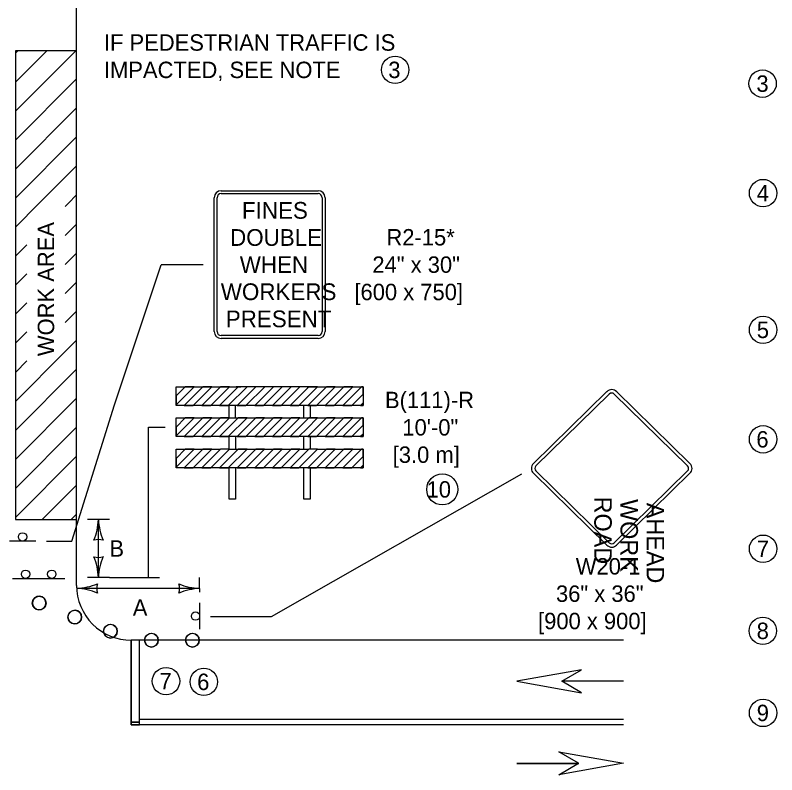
# Model space of a CAD drawing. Extents: x 49991.4 to 50021, y 49987.6 to 50011.4.
# Drawn here: x 50003.139 to 50005.923, y 50005.551 to 50008.327 of the extents above; entities that cross this region are included whole.
import ezdxf

# ---------------------------------------------------------------- set-up
doc = ezdxf.new("R2010")
doc.units = 0
for name, color, linetype in [('Level 1', 7, 'Continuous'), ('Level 2', 7, 'Continuous'), ('Level 3', 7, 'Continuous')]:
    doc.layers.add(name, color=color, linetype=linetype)

# ---------------------------------------------------------------- blocks, each defined once
blk = doc.blocks.new('ARR')
at = {"layer": 'Level 3'}
for centre, radius, start, end in [((1.53, 37.02), 37.05, 247.456, 267.6395), ((-21.37, 0), 9.13, 342.1388, 17.8612), ((1.92, -38.79), 38.83, 92.8273, 112.0772)]:
    blk.add_arc(centre, radius, start, end, dxfattribs=at)

msp = doc.modelspace()

# ---------------------------------------------------------------- linework, layer by layer
at = {"layer": 'Level 1'}
for p, q in [((50003.3635, 50006.2425), (50003.3635, 50008.3654)), ((50003.1396, 50008.1883), (50003.1483, 50008.197)), ((50003.1396, 50008.0822), (50003.2544, 50008.197)), ((50003.1396, 50007.9761), (50003.3604, 50008.197)), ((50003.1396, 50007.8701), (50003.3635, 50008.094)), ((50003.1396, 50007.764), (50003.3635, 50007.9879)), ((50003.1396, 50007.6579), (50003.3635, 50007.8818)), ((50003.2258, 50007.6381), (50003.3635, 50007.7758)), ((50003.8922, 50007.6852), (50004.2466, 50007.6852)), ((50003.8922, 50007.6747), (50004.2466, 50007.6747)), ((50004.0694, 50007.6852), (50004.0694, 50007.6852)), ((50003.3325, 50007.6387), (50003.3635, 50007.6697)), ((50003.8668, 50007.1705), (50003.8668, 50007.6599)), ((50003.8774, 50007.1705), (50003.8774, 50007.6599)), ((50004.2614, 50007.6599), (50004.2614, 50007.1705)), ((50004.2719, 50007.6599), (50004.2719, 50007.1705)), ((50003.1396, 50007.5519), (50003.2258, 50007.6381)), ((50003.3215, 50007.6278), (50003.3325, 50007.6387)), ((50003.3215, 50007.5217), (50003.3635, 50007.5636)), ((50003.1396, 50007.4458), (50003.1815, 50007.4878)), ((50003.3215, 50007.4156), (50003.3635, 50007.4576)), ((50003.1396, 50007.3397), (50003.1815, 50007.3817)), ((50003.3215, 50007.3096), (50003.3635, 50007.3515)), ((50003.1396, 50007.2337), (50003.1815, 50007.2756)), ((50003.3215, 50007.2035), (50003.3635, 50007.2454)), ((50003.1396, 50007.1276), (50003.1815, 50007.1696)), ((50004.2466, 50007.1557), (50003.8922, 50007.1557)), ((50004.2466, 50007.1452), (50003.8922, 50007.1452)), ((50003.3215, 50007.0974), (50003.3635, 50007.1394)), ((50003.1396, 50006.9155), (50003.3215, 50007.0974)), ((50003.1396, 50007.0215), (50003.1815, 50007.0635)), ((50003.1396, 50006.8094), (50003.3635, 50007.0333)), ((50003.7274, 50006.9029), (50003.7932, 50006.9687)), ((50003.7274, 50006.9351), (50003.761, 50006.9687)), ((50003.761, 50006.9687), (50003.7274, 50006.9351)), ((50003.7274, 50006.9029), (50003.7932, 50006.9687)), ((50003.7571, 50006.9003), (50003.8255, 50006.9687)), ((50003.8255, 50006.9687), (50003.7571, 50006.9003)), ((50003.7893, 50006.9003), (50003.8577, 50006.9687)), ((50003.7893, 50006.9003), (50003.8577, 50006.9687)), ((50003.8216, 50006.9003), (50003.89, 50006.9687)), ((50003.89, 50006.9687), (50003.8216, 50006.9003)), ((50003.8538, 50006.9003), (50003.9222, 50006.9687)), ((50003.8538, 50006.9003), (50003.9222, 50006.9687)), ((50003.886, 50006.9003), (50003.9544, 50006.9687)), ((50003.9183, 50006.9003), (50003.9867, 50006.9687)), ((50003.9326, 50006.9687), (50003.9639, 50006.9687)), ((50004.1919, 50006.9687), (50003.9468, 50006.9687)), ((50003.9507, 50006.9003), (50004.0191, 50006.9687)), ((50003.9829, 50006.9003), (50004.0513, 50006.9687)), ((50004.0151, 50006.9003), (50004.0835, 50006.9687)), ((50004.0473, 50006.9003), (50004.1157, 50006.9687)), ((50004.0795, 50006.9003), (50004.1479, 50006.9687)), ((50004.1117, 50006.9003), (50004.1801, 50006.9687)), ((50004.1439, 50006.9003), (50004.2123, 50006.9687)), ((50004.2123, 50006.9687), (50004.1724, 50006.9687)), ((50004.1761, 50006.9003), (50004.2445, 50006.9687)), ((50004.2084, 50006.9003), (50004.2768, 50006.9687)), ((50004.2768, 50006.9687), (50004.2084, 50006.9003)), ((50004.2406, 50006.9003), (50004.309, 50006.9687)), ((50004.2406, 50006.9003), (50004.309, 50006.9687)), ((50004.2728, 50006.9003), (50004.3412, 50006.9687)), ((50004.3412, 50006.9687), (50004.2728, 50006.9003)), ((50004.3051, 50006.9003), (50004.3735, 50006.9687)), ((50004.3051, 50006.9003), (50004.3735, 50006.9687)), ((50004.3374, 50006.9003), (50004.4058, 50006.9687)), ((50004.4058, 50006.9687), (50004.3374, 50006.9003)), ((50005.0342, 50006.6884), (50005.3022, 50006.9509)), ((50005.338, 50006.9509), (50005.606, 50006.6884)), ((50003.1396, 50006.7034), (50003.3635, 50006.9272)), ((50004.3696, 50006.9003), (50004.4113, 50006.9421)), ((50004.3696, 50006.9003), (50004.4113, 50006.9421)), ((50005.0428, 50006.6796), (50005.3108, 50006.9422)), ((50005.3295, 50006.9422), (50005.5974, 50006.6796)), ((50003.944, 50006.8548), (50003.944, 50006.9003)), ((50004.1948, 50006.8548), (50004.1948, 50006.9003)), ((50004.4018, 50006.9003), (50004.4113, 50006.9098)), ((50004.4113, 50006.9098), (50004.4018, 50006.9003)), ((50003.7274, 50006.7889), (50003.7932, 50006.8548)), ((50003.7274, 50006.8211), (50003.761, 50006.8548)), ((50003.761, 50006.8548), (50003.7274, 50006.8211)), ((50003.7274, 50006.7889), (50003.7932, 50006.8548)), ((50003.7571, 50006.7864), (50003.8255, 50006.8548)), ((50003.8255, 50006.8548), (50003.7571, 50006.7864)), ((50003.7893, 50006.7864), (50003.8577, 50006.8548)), ((50003.7893, 50006.7864), (50003.8577, 50006.8548)), ((50003.8216, 50006.7864), (50003.89, 50006.8548)), ((50003.89, 50006.8548), (50003.8216, 50006.7864)), ((50003.8538, 50006.7864), (50003.9222, 50006.8548)), ((50003.8538, 50006.7864), (50003.9222, 50006.8548)), ((50003.886, 50006.7864), (50003.9544, 50006.8548)), ((50003.9183, 50006.7864), (50003.9867, 50006.8548)), ((50003.9505, 50006.7864), (50004.0189, 50006.8548)), ((50003.9827, 50006.7864), (50004.0511, 50006.8548)), ((50004.0149, 50006.7864), (50004.0833, 50006.8548)), ((50004.0472, 50006.7864), (50004.1156, 50006.8548)), ((50004.0795, 50006.7864), (50004.1479, 50006.8548)), ((50004.1117, 50006.7864), (50004.1801, 50006.8548)), ((50004.1439, 50006.7864), (50004.2062, 50006.8486)), ((50004.2062, 50006.8164), (50004.2445, 50006.8548)), ((50004.2062, 50006.8486), (50004.2123, 50006.8548)), ((50004.2084, 50006.7864), (50004.2768, 50006.8548)), ((50004.2768, 50006.8548), (50004.2084, 50006.7864)), ((50004.2406, 50006.7864), (50004.309, 50006.8548)), ((50004.2406, 50006.7864), (50004.309, 50006.8548)), ((50004.2728, 50006.7864), (50004.3412, 50006.8548)), ((50004.3412, 50006.8548), (50004.2728, 50006.7864)), ((50004.3051, 50006.7864), (50004.3735, 50006.8548)), ((50004.3051, 50006.7864), (50004.3735, 50006.8548)), ((50004.3374, 50006.7864), (50004.4058, 50006.8548)), ((50004.4058, 50006.8548), (50004.3374, 50006.7864)), ((50003.1396, 50006.5973), (50003.3635, 50006.8212)), ((50004.1761, 50006.7864), (50004.2062, 50006.8164)), ((50004.3696, 50006.7864), (50004.4113, 50006.8281)), ((50004.3696, 50006.7864), (50004.4113, 50006.8281)), ((50004.4018, 50006.7864), (50004.4113, 50006.7959)), ((50004.4113, 50006.7959), (50004.4018, 50006.7864)), ((50003.7274, 50006.6749), (50003.7932, 50006.7408)), ((50003.7274, 50006.7072), (50003.761, 50006.7408)), ((50003.761, 50006.7408), (50003.7274, 50006.7072)), ((50003.7274, 50006.6749), (50003.7932, 50006.7408)), ((50003.7571, 50006.6724), (50003.8255, 50006.7408)), ((50003.8255, 50006.7408), (50003.7571, 50006.6724)), ((50003.7893, 50006.6724), (50003.8577, 50006.7408)), ((50003.7893, 50006.6724), (50003.8577, 50006.7408)), ((50003.8216, 50006.6724), (50003.89, 50006.7408)), ((50003.89, 50006.7408), (50003.8216, 50006.6724)), ((50003.8538, 50006.6724), (50003.9222, 50006.7408)), ((50003.8538, 50006.6724), (50003.9222, 50006.7408)), ((50003.886, 50006.6724), (50003.9544, 50006.7408)), ((50003.9544, 50006.7408), (50003.886, 50006.6724)), ((50003.9183, 50006.6724), (50003.9867, 50006.7408)), ((50003.9183, 50006.6724), (50003.9867, 50006.7408)), ((50003.9505, 50006.6724), (50004.0189, 50006.7408)), ((50004.0189, 50006.7408), (50003.9505, 50006.6724)), ((50003.9827, 50006.6724), (50004.0511, 50006.7408)), ((50003.9827, 50006.6724), (50004.0511, 50006.7408)), ((50004.0149, 50006.6724), (50004.0833, 50006.7408)), ((50004.0833, 50006.7408), (50004.0149, 50006.6724)), ((50004.0472, 50006.6724), (50004.1156, 50006.7408)), ((50004.0472, 50006.6724), (50004.1156, 50006.7408)), ((50004.0795, 50006.6724), (50004.1479, 50006.7408)), ((50004.1479, 50006.7408), (50004.0795, 50006.6724)), ((50004.1117, 50006.6724), (50004.1801, 50006.7408)), ((50004.1117, 50006.6724), (50004.1801, 50006.7408)), ((50004.1439, 50006.6724), (50004.2123, 50006.7408)), ((50004.2123, 50006.7408), (50004.1439, 50006.6724)), ((50004.1761, 50006.6724), (50004.2445, 50006.7408)), ((50004.1761, 50006.6724), (50004.2445, 50006.7408)), ((50004.2084, 50006.6724), (50004.2768, 50006.7408)), ((50004.2768, 50006.7408), (50004.2084, 50006.6724)), ((50004.2406, 50006.6724), (50004.309, 50006.7408)), ((50004.2406, 50006.6724), (50004.309, 50006.7408)), ((50004.2728, 50006.6724), (50004.3412, 50006.7408)), ((50004.3412, 50006.7408), (50004.2728, 50006.6724)), ((50004.3051, 50006.6724), (50004.3735, 50006.7408)), ((50004.3051, 50006.6724), (50004.3735, 50006.7408)), ((50004.3374, 50006.6724), (50004.4058, 50006.7408)), ((50004.4058, 50006.7408), (50004.3374, 50006.6724)), ((50003.1396, 50006.4912), (50003.3635, 50006.7151)), ((50004.3696, 50006.6724), (50004.4113, 50006.7141)), ((50004.3696, 50006.6724), (50004.4113, 50006.7141)), ((50004.4018, 50006.6724), (50004.4113, 50006.6819)), ((50004.4113, 50006.6819), (50004.4018, 50006.6724)), ((50005.3022, 50006.3899), (50005.0342, 50006.6525)), ((50005.3108, 50006.3987), (50005.0428, 50006.6612)), ((50005.5974, 50006.6612), (50005.3295, 50006.3987)), ((50005.606, 50006.6525), (50005.338, 50006.3899)), ((50003.238, 50006.4836), (50003.3635, 50006.609)), ((50003.3441, 50006.4836), (50003.3635, 50006.503)), ((50003.2141, 50006.405), (50003.1181, 50006.405)), ((50003.1288, 50006.2684), (50003.2248, 50006.2684)), ((50003.2248, 50006.2684), (50003.3208, 50006.2684)), ((50003.8135, 50006.1786), (50003.8135, 50006.0826)), ((50005.3635, 50006.0426), (50003.5635, 50006.0426)), ((50003.5635, 50005.7326), (50003.5635, 50006.0426)), ((50003.5935, 50005.7326), (50003.5935, 50006.0426)), ((50005.3635, 50005.8927), (50005.1376, 50005.8927)), ((50005.3635, 50005.8923), (50005.1376, 50005.8923)), ((50005.3635, 50005.7526), (50003.5935, 50005.7526)), ((50003.5935, 50005.7427), (50003.5635, 50005.7427)), ((50005.3635, 50005.7326), (50003.5635, 50005.7326)), ((50004.9734, 50005.5927), (50005.1993, 50005.5927)), ((50004.9734, 50005.5923), (50005.1993, 50005.5923))]:
    msp.add_line(p, q, dxfattribs=at)
for points in [[(50003.3635, 50008.197), (50003.1396, 50008.197), (50003.1396, 50006.4836), (50003.3635, 50006.4836)], [(50004.2062, 50006.9003), (50003.7274, 50006.9003), (50003.7274, 50006.9687), (50003.9326, 50006.9687)], [(50003.7932, 50006.9687), (50003.761, 50006.9687)], [(50003.8577, 50006.9687), (50003.8255, 50006.9687)], [(50003.9867, 50006.9687), (50003.9639, 50006.9687), (50003.9544, 50006.9687), (50003.886, 50006.9003), (50003.9183, 50006.9003), (50003.9867, 50006.9687)], [(50003.9222, 50006.9687), (50003.89, 50006.9687)], [(50004.0513, 50006.9687), (50004.0191, 50006.9687), (50003.9507, 50006.9003), (50003.9829, 50006.9003), (50004.0513, 50006.9687)], [(50004.1157, 50006.9687), (50004.0835, 50006.9687), (50004.0151, 50006.9003), (50004.0473, 50006.9003), (50004.1157, 50006.9687)], [(50004.1801, 50006.9687), (50004.1724, 50006.9687), (50004.1479, 50006.9687), (50004.0795, 50006.9003), (50004.1117, 50006.9003), (50004.1801, 50006.9687)], [(50004.1439, 50006.9003), (50004.1761, 50006.9003), (50004.2445, 50006.9687), (50004.2123, 50006.9687), (50004.1439, 50006.9003)], [(50004.2062, 50006.9687), (50004.4113, 50006.9687), (50004.4113, 50006.9003), (50004.2062, 50006.9003)], [(50004.309, 50006.9687), (50004.2768, 50006.9687)], [(50004.3735, 50006.9687), (50004.3412, 50006.9687)], [(50004.4113, 50006.9421), (50004.4113, 50006.9687), (50004.4058, 50006.9687)], [(50003.7274, 50006.9351), (50003.7274, 50006.9029)], [(50003.7571, 50006.9003), (50003.7893, 50006.9003)], [(50003.8216, 50006.9003), (50003.8538, 50006.9003)], [(50003.9212, 50006.8547), (50003.9212, 50006.9003)], [(50004.2084, 50006.9003), (50004.2406, 50006.9003)], [(50004.2176, 50006.9003), (50004.2176, 50006.8548)], [(50004.2728, 50006.9003), (50004.3051, 50006.9003)], [(50004.3374, 50006.9003), (50004.3696, 50006.9003)], [(50004.4018, 50006.9003), (50004.4113, 50006.9003), (50004.4113, 50006.9098)], [(50004.2062, 50006.8548), (50004.4113, 50006.8548), (50004.4113, 50006.7864), (50003.7274, 50006.7864), (50003.7274, 50006.8548), (50004.2062, 50006.8548)], [(50003.7932, 50006.8548), (50003.761, 50006.8548)], [(50003.8577, 50006.8548), (50003.8255, 50006.8548)], [(50003.9867, 50006.8548), (50003.9544, 50006.8548), (50003.886, 50006.7864), (50003.9183, 50006.7864), (50003.9867, 50006.8548)], [(50003.9222, 50006.8548), (50003.89, 50006.8548)], [(50004.0511, 50006.8548), (50004.0189, 50006.8548), (50003.9505, 50006.7864), (50003.9827, 50006.7864), (50004.0511, 50006.8548)], [(50004.1156, 50006.8548), (50004.0833, 50006.8548), (50004.0149, 50006.7864), (50004.0472, 50006.7864), (50004.1156, 50006.8548)], [(50004.1801, 50006.8548), (50004.1479, 50006.8548), (50004.0795, 50006.7864), (50004.1117, 50006.7864), (50004.1801, 50006.8548)], [(50004.1439, 50006.7864), (50004.1761, 50006.7864), (50004.2062, 50006.8164), (50004.2445, 50006.8548), (50004.2176, 50006.8548), (50004.2123, 50006.8548), (50004.2062, 50006.8486), (50004.1439, 50006.7864)], [(50004.309, 50006.8548), (50004.2768, 50006.8548)], [(50004.3735, 50006.8548), (50004.3412, 50006.8548)], [(50004.4113, 50006.8281), (50004.4113, 50006.8548), (50004.4058, 50006.8548)], [(50003.7274, 50006.8211), (50003.7274, 50006.7889)], [(50003.7571, 50006.7864), (50003.7893, 50006.7864)], [(50003.8216, 50006.7864), (50003.8538, 50006.7864)], [(50003.9212, 50006.7408), (50003.9212, 50006.7864)], [(50003.944, 50006.7864), (50003.944, 50006.7408)], [(50004.1948, 50006.7408), (50004.1948, 50006.7864)], [(50004.2084, 50006.7864), (50004.2406, 50006.7864)], [(50004.2176, 50006.7864), (50004.2176, 50006.7408)], [(50004.2728, 50006.7864), (50004.3051, 50006.7864)], [(50004.3374, 50006.7864), (50004.3696, 50006.7864)], [(50004.4018, 50006.7864), (50004.4113, 50006.7864), (50004.4113, 50006.7959)], [(50004.2445, 50006.7408), (50004.4113, 50006.7408), (50004.4113, 50006.6724), (50003.7274, 50006.6724), (50003.7274, 50006.7408), (50003.89, 50006.7408)], [(50003.7932, 50006.7408), (50003.761, 50006.7408)], [(50003.8577, 50006.7408), (50003.8255, 50006.7408)], [(50003.9222, 50006.7408), (50003.89, 50006.7408)], [(50003.9222, 50006.7408), (50004.2123, 50006.7408)], [(50003.9867, 50006.7408), (50003.9544, 50006.7408)], [(50004.0511, 50006.7408), (50004.0189, 50006.7408)], [(50004.1156, 50006.7408), (50004.0833, 50006.7408)], [(50004.1801, 50006.7408), (50004.1479, 50006.7408)], [(50004.2445, 50006.7408), (50004.2123, 50006.7408)], [(50004.309, 50006.7408), (50004.2768, 50006.7408)], [(50004.3735, 50006.7408), (50004.3412, 50006.7408)], [(50004.4113, 50006.7141), (50004.4113, 50006.7408), (50004.4058, 50006.7408)], [(50003.7274, 50006.7072), (50003.7274, 50006.6749)], [(50003.7571, 50006.6724), (50003.7893, 50006.6724)], [(50003.8216, 50006.6724), (50003.8538, 50006.6724)], [(50003.886, 50006.6724), (50003.9183, 50006.6724)], [(50003.944, 50006.6723), (50003.944, 50006.5583), (50003.9212, 50006.5583), (50003.9212, 50006.6723)], [(50003.9505, 50006.6724), (50003.9827, 50006.6724)], [(50004.0149, 50006.6724), (50004.0472, 50006.6724)], [(50004.0795, 50006.6724), (50004.1117, 50006.6724)], [(50004.1439, 50006.6724), (50004.1761, 50006.6724)], [(50004.2176, 50006.6723), (50004.2176, 50006.5583), (50004.1948, 50006.5583), (50004.1948, 50006.6723)], [(50004.2084, 50006.6724), (50004.2406, 50006.6724)], [(50004.2728, 50006.6724), (50004.3051, 50006.6724)], [(50004.3374, 50006.6724), (50004.3696, 50006.6724)], [(50004.4018, 50006.6724), (50004.4113, 50006.6724), (50004.4113, 50006.6819)], [(50003.5935, 50006.0426), (50003.5635, 50006.0426), (50003.5635, 50005.7427), (50003.5935, 50005.7427), (50003.5935, 50006.0426)], [(50003.5635, 50005.7427), (50003.5635, 50005.7326), (50003.5935, 50005.7326), (50003.5935, 50005.7427), (50003.5635, 50005.7427)]]:
    msp.add_lwpolyline(points, dxfattribs=at)
for points in [[(50005.2099, 50005.9343), (50004.9734, 50005.8927), (50005.2099, 50005.8507), (50005.1377, 50005.8927)], [(50005.127, 50005.6343), (50005.3635, 50005.5927), (50005.127, 50005.5507), (50005.1992, 50005.5927)]]:
    msp.add_lwpolyline(points, close=True, dxfattribs=at)
for centre, radius in [((50003.1661, 50006.4202), 0.0152), ((50003.1768, 50006.2836), 0.0152), ((50003.2728, 50006.2836), 0.0152), ((50003.2267, 50006.1783), 0.025), ((50003.3569, 50006.1269), 0.025), ((50003.7983, 50006.1306), 0.0152), ((50003.4872, 50006.0755), 0.025), ((50003.6372, 50006.0426), 0.025), ((50003.7872, 50006.0426), 0.025)]:
    msp.add_circle(centre, radius, dxfattribs=at)
for centre, radius, start, end in [((50003.8922, 50007.6599), 0.0253, 90, 180), ((50003.8922, 50007.6599), 0.0148, 90, 180), ((50004.2466, 50007.6599), 0.0253, 0, 90), ((50004.2466, 50007.6599), 0.0148, 0, 90), ((50003.8922, 50007.1705), 0.0253, 180, 270), ((50003.8922, 50007.1705), 0.0148, 180, 270), ((50004.2466, 50007.1705), 0.0148, 270, 360), ((50004.2466, 50007.1705), 0.0253, 270, 360), ((50003.5635, 50006.2426), 0.2, 180, 270.0006), ((50003.2267, 50006.1783), 0.025, 357.0759, 177.0759), ((50003.2267, 50006.1783), 0.025, 177.0759, 357.0759), ((50003.3569, 50006.1269), 0.025, 357.0759, 177.0759), ((50003.3569, 50006.1269), 0.025, 177.0759, 357.0759), ((50003.4872, 50006.0755), 0.025, 357.0759, 177.0759), ((50003.4872, 50006.0755), 0.025, 177.0759, 357.0759), ((50003.6372, 50006.0426), 0.025, 357.0759, 177.0759), ((50003.7872, 50006.0426), 0.025, 357.0759, 177.0759), ((50003.6372, 50006.0426), 0.025, 177.0759, 357.0759), ((50003.7872, 50006.0426), 0.025, 177.0759, 357.0759)]:
    msp.add_arc(centre, radius, start, end, dxfattribs=at)
for centre, major_axis, ratio, start_param, end_param in [((50005.3202, 50006.933), (-0.0255, 0), 0.98963, 3.926991, 5.497787), ((50005.3202, 50006.933), (-0.0132, 0), 0.98, 3.926991, 5.497787), ((50005.0522, 50006.6704), (-0.0255, 0), 0.98963, 5.497787, 7.068583), ((50005.0522, 50006.6704), (-0.0132, 0), 0.98, 5.497787, 7.068583), ((50005.5881, 50006.6704), (0.0132, 0), 0.98, 5.497795, 7.068583), ((50005.5881, 50006.6704), (0.0255, 0), 0.98963, 5.497795, 7.068583), ((50005.3202, 50006.4078), (-0.0132, 0), 0.98, 0.785394, 2.356194), ((50005.3202, 50006.4078), (-0.0255, 0), 0.98963, 0.785394, 2.356194)]:
    msp.add_ellipse(centre, major_axis=major_axis, ratio=ratio, start_param=start_param, end_param=end_param, dxfattribs=at)
at = {"layer": 'Level 2'}
for centre, radius in [((50004.5284, 50008.127), 0.0501), ((50005.8718, 50008.0767), 0.0501), ((50005.8734, 50007.6767), 0.0501), ((50005.8734, 50007.1767), 0.0501), ((50005.8734, 50006.7767), 0.0501), ((50004.7007, 50006.5937), 0.0569), ((50005.8734, 50006.3767), 0.0501), ((50005.8728, 50006.0767), 0.0501), ((50003.6905, 50005.8928), 0.0501), ((50003.8289, 50005.8903), 0.0501), ((50005.8734, 50005.7767), 0.0501)]:
    msp.add_circle(centre, radius, dxfattribs=at)
at = {"layer": 'Level 3'}
for p, q in [((50003.502, 50006.9032), (50003.6726, 50007.4142)), ((50003.6726, 50007.4152), (50003.8268, 50007.4152)), ((50003.3463, 50006.405), (50003.502, 50006.9032)), ((50003.6267, 50006.8206), (50003.6874, 50006.8206)), ((50003.6267, 50006.2717), (50003.6267, 50006.8206)), ((50004.0767, 50006.129), (50004.992, 50006.6506)), ((50003.4835, 50006.4836), (50003.4035, 50006.4836)), ((50003.4435, 50006.2717), (50003.4435, 50006.4836)), ((50003.2541, 50006.405), (50003.3463, 50006.405)), ((50003.4835, 50006.2717), (50003.4035, 50006.2717)), ((50003.4835, 50006.2717), (50003.6667, 50006.2717)), ((50003.8135, 50006.2317), (50003.8135, 50006.2717)), ((50003.8135, 50006.2317), (50003.3638, 50006.2317)), ((50003.8135, 50006.2317), (50003.8135, 50006.2186)), ((50003.8535, 50006.129), (50004.0767, 50006.129))]:
    msp.add_line(p, q, dxfattribs=at)
for centre, radius, start, end in [((50003.2213, 50006.4928), 0.2223, 337.456, 357.6395), ((50003.6762, 50006.4951), 0.233, 182.8273, 202.0772), ((50003.4435, 50006.3554), 0.0548, 72.1388, 107.8612), ((50003.4435, 50006.3999), 0.0548, 252.1388, 287.8612), ((50003.2108, 50006.2602), 0.233, 2.8273, 22.0772), ((50003.6656, 50006.2626), 0.2223, 157.456, 177.6395)]:
    msp.add_arc(centre, radius, start, end, dxfattribs=at)

# ---------------------------------------------------------------- block references
at = {"layer": 'Level 3', "xscale": 0.006, "yscale": 0.006, "rotation": 180}
msp.add_blockref('ARR', (50003.3638, 50006.2317), dxfattribs=at)
at = {"layer": 'Level 3', "xscale": 0.006, "yscale": 0.006}
msp.add_blockref('ARR', (50003.8135, 50006.2317), dxfattribs=at)

# ---------------------------------------------------------------- texts
at = {"layer": 'Level 1'}
for s, p in [('FINES', (50003.9682, 50007.5829)), ('DOUBLE', (50003.9247, 50007.4838)), ('WHEN', (50003.9602, 50007.3846)), ('WORKERS', (50003.8908, 50007.2855)), ('PRESENT', (50003.9089, 50007.1863))]:
    msp.add_text(s, height=0.06118, dxfattribs=at).set_placement(p)
for s, p in [('ROAD', (50005.2563, 50006.5673)), ('WORK', (50005.3521, 50006.5583)), ('AHEAD', (50005.4478, 50006.5447))]:
    msp.add_text(s, height=0.06389, rotation=270, dxfattribs=at).set_placement(p)
at = {"layer": 'Level 2'}
for s, p in [('IF PEDESTRIAN TRAFFIC IS ', (50003.4635, 50008.197)), ('IMPACTED, SEE NOTE', (50003.4635, 50008.097)), ('3', (50004.5032, 50008.097)), ('3', (50005.849, 50008.0467)), ('4', (50005.8505, 50007.6467)), ('R2-15*', (50004.4964, 50007.4852)), ('24" x 30"', (50004.4449, 50007.3852)), ('[600 x 750]', (50004.3793, 50007.2852)), ('5', (50005.8505, 50007.1467)), ('B(111)-R', (50004.4911, 50006.8906)), ('10\'-0"', (50004.5546, 50006.7906)), ('6', (50005.8489, 50006.7467)), ('[3.0 m]', (50004.5193, 50006.6906)), ('10', (50004.6432, 50006.5637)), ('B', (50003.4835, 50006.3477)), ('7', (50005.8505, 50006.3467)), ('W20-1', (50005.1886, 50006.2826)), ('36" x 36"', (50005.1163, 50006.1826)), ('A', (50003.569, 50006.1317)), ('[900 x 900]', (50005.0507, 50006.0826)), ('8', (50005.85, 50006.0467)), ('7', (50003.6667, 50005.8628)), ('6', (50003.8044, 50005.8603)), ('9', (50005.8503, 50005.7467))]:
    msp.add_text(s, height=0.06, dxfattribs=at).set_placement(p)
msp.add_text('WORK AREA', height=0.06, rotation=90, dxfattribs=at).set_placement((50003.2815, 50007.0807))

doc.saveas('drawing.dxf')
